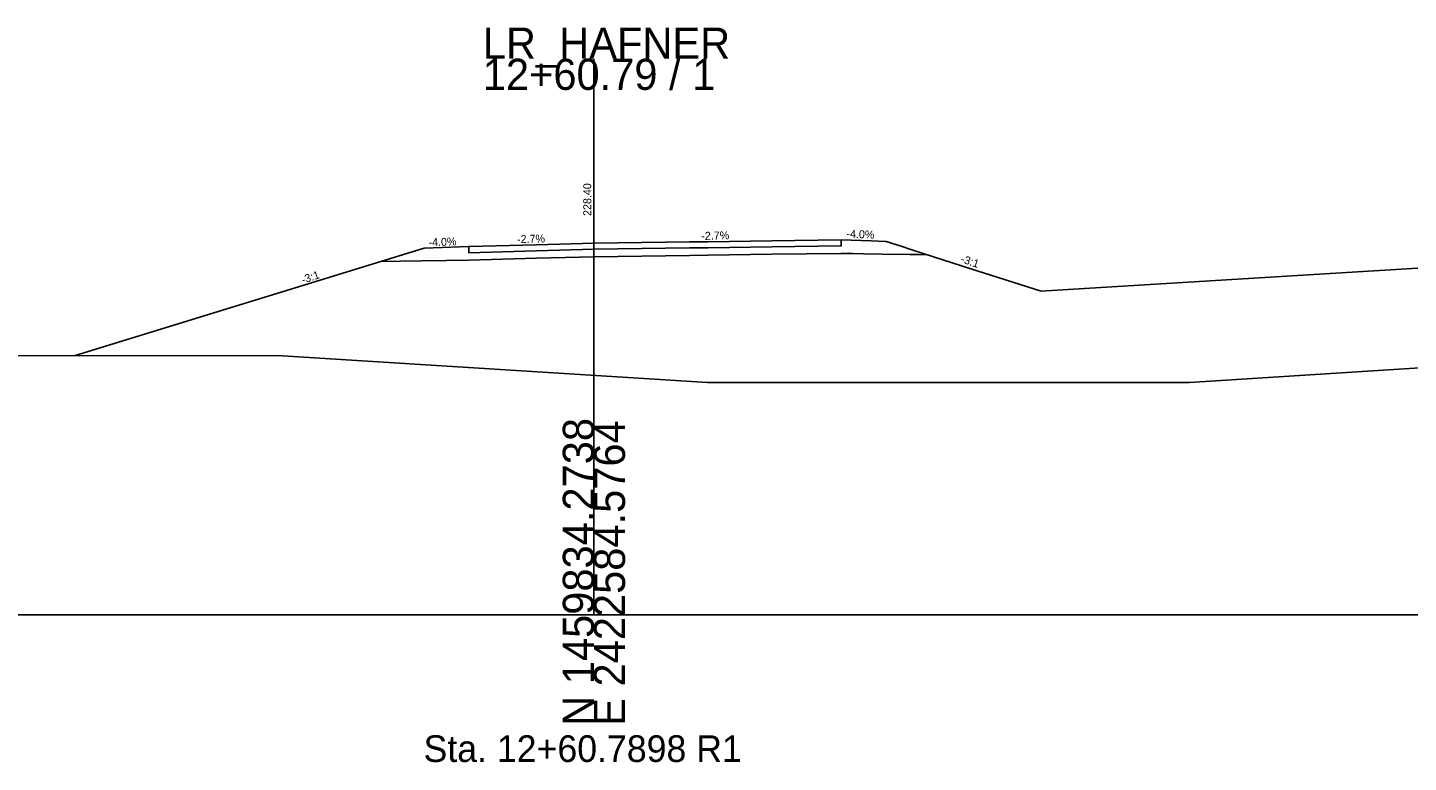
# Model space of a CAD drawing. Extents: x -26 to 403, y -13 to 3053.
# Drawn here: x 149 to 273.3, y 2986.7 to 3052.8 of the extents above; entities that cross this region are included whole.
import ezdxf

# ---------------------------------------------------------------- set-up
doc = ezdxf.new("R2010")
doc.units = 0
for name, color, linetype in [('Draft_XS_Text', 7, 'Continuous'), ('DTM_CORRIDOR', 7, 'Continuous'), ('DTM_P_FINISHED_GRADE', 7, 'Continuous'), ('DTM_TEMP_DROP', 7, 'Continuous'), ('DTM_X_GROUND', 7, 'Continuous'), ('XS_CELL', 7, 'Continuous'), ('XS_P_ASPHALT', 7, 'Continuous'), ('XS_P_GROUND', 7, 'Continuous'), ('XS_P_SHOULDER', 7, 'Continuous'), ('XS_P_SUBGRADE_GRANULAR', 7, 'Continuous'), ('XS_P_TX_CLEARZONE', 7, 'Continuous'), ('XS_P_TX_FS_BS', 7, 'Continuous')]:
    doc.layers.add(name, color=color, linetype=linetype)

msp = doc.modelspace()

# ---------------------------------------------------------------- linework, layer by layer
at = {"layer": 'DTM_P_FINISHED_GRADE'}
for points in [[(188.75, 3033.1), (194.82, 3033.26), (200, 3033.4)], [(200, 3033.4), (208.6, 3033.52), (210.28, 3033.54), (216.01, 3033.62), (222.26, 3033.7)]]:
    msp.add_lwpolyline(points, dxfattribs=at)
at = {"layer": 'DTM_X_GROUND'}
msp.add_lwpolyline([(126.89, 3023.31), (171.98, 3023.29), (210.21, 3020.88), (253.58, 3020.87), (274.78, 3022.22), (283.01, 3023.5), (297.39, 3025.12), (308.37, 3028), (324.19, 3034.2), (327.5, 3034.26), (337.03, 3034.67), (351.44, 3035.4), (371.24, 3036.18), (372.84, 3036.24), (382.88, 3036.54), (400, 3036.86)], dxfattribs=at)
at = {"layer": 'XS_CELL'}
for p, q in [((200, 3000), (200, 3050)), ((0, 3000), (200, 3000)), ((200, 3000), (400, 3000))]:
    msp.add_line(p, q, dxfattribs=at)
at = {"layer": 'XS_P_ASPHALT'}
for points in [[(188.75, 3033.1), (188.75, 3032.55), (194.82, 3032.72), (200, 3032.86), (200, 3033.4), (194.82, 3033.26), (188.75, 3033.1)], [(200, 3033.4), (200, 3032.86), (208.6, 3032.98), (210.28, 3033), (216.01, 3033.08), (222.26, 3033.16), (222.26, 3033.7), (216.01, 3033.62), (210.28, 3033.54), (208.6, 3033.52), (200, 3033.4)]]:
    msp.add_lwpolyline(points, dxfattribs=at)
at = {"layer": 'XS_P_GROUND'}
for p, q in [((240.21, 3029.09), (324.19, 3034.2)), ((184.72, 3032.97), (153.33, 3023.3))]:
    msp.add_line(p, q, dxfattribs=at)
msp.add_lwpolyline([(240.25, 3029.1), (237.12, 3030.08), (236.37, 3030.32), (235.05, 3030.74), (234, 3031.07), (229.62, 3032.49), (228.44, 3032.87), (227.74, 3033.1), (226.29, 3033.57)], dxfattribs=at)
at = {"layer": 'XS_P_SHOULDER'}
for points in [[(184.72, 3032.97), (188.75, 3033.1)], [(226.29, 3033.57), (224.96, 3033.61), (222.26, 3033.7)]]:
    msp.add_lwpolyline(points, dxfattribs=at)
at = {"layer": 'XS_P_SUBGRADE_GRANULAR'}
for points in [[(180.83, 3031.77), (182.56, 3031.8), (184.51, 3031.82), (186.73, 3031.86), (188.75, 3031.89), (188.75, 3031.89)], [(188.75, 3031.89), (194.82, 3032.05), (200, 3032.19)], [(200, 3032.19), (208.6, 3032.31), (210.28, 3032.34), (216.01, 3032.41), (222.26, 3032.49)], [(229.97, 3032.37), (229.31, 3032.38), (228.44, 3032.4), (225.94, 3032.43), (224.27, 3032.46), (223.29, 3032.48), (222.26, 3032.49)]]:
    msp.add_lwpolyline(points, dxfattribs=at)

# ---------------------------------------------------------------- texts
at = {"layer": 'Draft_XS_Text'}
msp.add_text('Sta. 12+60.7898 R1', height=2.4, dxfattribs=at).set_placement((184.67, 2986.75))
at = {"layer": 'DTM_CORRIDOR'}
for p in [(184.71, 3032.96), (215.28, 3033.36), (215.28, 3033.36), (226.28, 3033.57)]:
    msp.add_text('X', height=0.012, dxfattribs=at).set_placement(p)
at = {"layer": 'DTM_TEMP_DROP'}
for p in [(184.71, 3032.96), (215.28, 3033.36), (215.28, 3033.36), (222.26, 3033.69), (226.28, 3033.57)]:
    msp.add_text('X', height=0.012, dxfattribs=at).set_placement(p)
at = {"layer": 'XS_CELL'}
for s, p in [('LR_HAFNER', (190, 3050)), ('12+60.79 / 1', (190, 3047.2))]:
    msp.add_text(s, height=2.8, dxfattribs=at).set_placement(p)
for s, p in [('N 1459834.2738', (200, 2990)), ('E 2422584.5764', (202.8, 2990))]:
    msp.add_text(s, height=2.8, rotation=90, dxfattribs=at).set_placement(p)
at = {"layer": 'XS_P_TX_CLEARZONE'}
msp.add_text('228.40', height=0.72, rotation=90, dxfattribs=at).set_placement((199.76, 3035.86))
msp.add_text('228.40', height=0.72, rotation=90, dxfattribs=at).set_placement((199.76, 3035.86))
at = {"layer": 'XS_P_TX_FS_BS'}
for s, rotation, p in [('-4.0%', 2.2906, (185.13, 3033.12)), ('-2.7%', 1.5674, (193.09, 3033.41)), ('-2.7%', 1.5674, (209.67, 3033.7)), ('-4.0%', 357.7096, (222.71, 3033.91)), ('-3:1', 341.5653, (232.94, 3031.71)), ('-3:1', 18.4349, (173.81, 3029.75)), ('-3:1', 18.4349, (173.81, 3029.75))]:
    msp.add_text(s, height=0.72, rotation=rotation, dxfattribs=at).set_placement(p)

doc.saveas('drawing.dxf')
